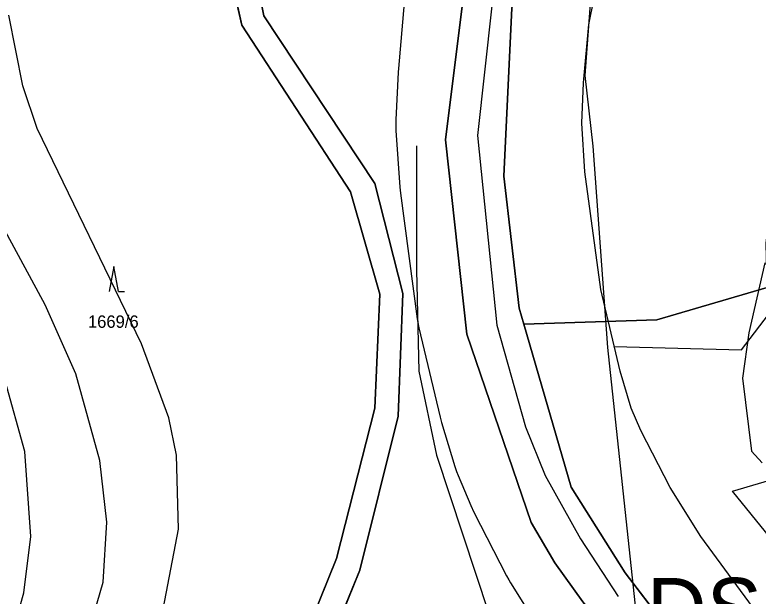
# Model space of a CAD drawing. Extents: x -706130 to -698555, y -971544 to -967260.
# Drawn here: x -704475.2 to -704355.2, y -970876.8 to -970782.9 of the extents above; entities that cross this region are included whole.
import ezdxf

# ---------------------------------------------------------------- set-up
doc = ezdxf.new("R2010")
doc.units = 0
for name, color, linetype in [('KN_Hranice_parcel', 7, 'Continuous'), ('KN_Parcelni cisla', 7, 'Continuous'), ('KN_Polygon parcely', 7, 'Continuous'), ('KN_POZEMKY_10_LESNI POZEMEK', 7, 'Continuous'), ('KN_POZEMKY_14_OSTATNI PLOCHA', 7, 'Continuous'), ('KN_VYUZITI_16_ostatni plocha_silnice', 7, 'Continuous'), ('KN_VYUZITI_17_ostatni plocha_ostatni komunikace', 7, 'Continuous'), ('KN_VYUZITI_26_ostatni plocha_jina plocha', 7, 'Continuous'), ('KN_Značky kultur', 7, 'Continuous'), ('Komunikace III třídy osy S', 7, 'Continuous'), ('OP lesa 30 m', 7, 'Continuous'), ('OP silnic S', 7, 'Continuous'), ('Plochy doprava silniční - silnice III třídy S', 7, 'Continuous'), ('Plochy lesní všeobecné S', 7, 'Continuous'), ('Plochy přírodní - lesní S', 7, 'Continuous'), ('Plochy přírodní - nelesní S', 7, 'Continuous'), ('Plochy těžby nerostů - jiné S', 7, 'Continuous'), ('Regulační bloky v krajině S', 7, 'Continuous'), ('Regulační bloky zastavěné S', 7, 'Continuous'), ('Regulační kódy zastavěné S', 7, 'Continuous'), ('Spoje_dálkový komunikační kabel S', 7, 'Continuous'), ('Trasy cykloturistické N', 7, 'Continuous'), ('USES_BC_mistni S', 7, 'Continuous'), ('USES_ŠRAFY S', 7, 'Continuous'), ('VÝŠKOPIS_vrstevnice doplňková', 7, 'Continuous'), ('VÝŠKOPIS_vrstevnice hlavní', 7, 'Continuous')]:
    doc.layers.add(name, color=color, linetype=linetype)

msp = doc.modelspace()

# ---------------------------------------------------------------- linework, layer by layer
at = {"layer": 'KN_Hranice_parcel'}
for points in [[(-704429.88, -970483.99), (-704437.86, -970500.93), (-704440.81, -970512.35), (-704444.18, -970537.3), (-704437.59, -970564.83), (-704389.48, -970641.61), (-704384.25, -970653.17), (-704379.8, -970666.04), (-704377.6, -970678.33), (-704377.41, -970702.19), (-704385.12, -970737.85), (-704395, -970781.85), (-704396.32, -970808.97), (-704393.81, -970830.29), (-704393.06, -970832.89)], [(-704394.53, -970717.38), (-704412.48, -970734.47), (-704417.24, -970746.67), (-704433.74, -970766.44), (-704437.24, -970771.29), (-704440.06, -970778.03), (-704438.61, -970784.59), (-704421.06, -970811.51), (-704416.31, -970828.02), (-704417.14, -970846.47), (-704423.32, -970870.73), (-704430.14, -970887.7), (-704441.3, -970904.25), (-704468.7, -970937.47), (-704474.31, -970946.68), (-704474.09, -970952.69), (-704473.62, -970956.96), (-704461.41, -971000.71)], [(-704358.88, -970998.11), (-704359.55, -970918.79), (-704364.6, -970901.09), (-704383.52, -970877.76), (-704388.05, -970871.47), (-704391.88, -970864.93), (-704402.29, -970834.53), (-704405.74, -970803.12), (-704402.86, -970780.15), (-704394.94, -970736.25), (-704391.73, -970719.71)], [(-704394.9, -970722.73), (-704407.89, -970735.14), (-704413.08, -970748.41), (-704429.87, -970768.12), (-704434.2, -970773.68), (-704436, -970778.11), (-704435.04, -970783.09), (-704417.14, -970810.17), (-704412.6, -970827.95), (-704413.35, -970847.75), (-704419.53, -970872.65), (-704427.42, -970891.79), (-704435.22, -970903.01), (-704464.78, -970939.11), (-704470.08, -970947.26), (-704470.3, -970952.41), (-704470.15, -970956.87), (-704458.51, -971000.63), (-704450.87, -971043.52)], [(-704393.06, -970832.89), (-704371.61, -970832.19), (-704353.77, -970826.96)], [(-704393.06, -970832.89), (-704385.45, -970859.24), (-704376.72, -970873.06), (-704355.73, -970900.46), (-704350.71, -970916.39), (-704350.59, -970954.64)]]:
    msp.add_lwpolyline(points, dxfattribs=at)
at = {"layer": 'KN_Polygon parcely'}
for points in [[(-704480.71, -970987.86), (-704461.41, -971000.71), (-704473.62, -970956.96), (-704474.09, -970952.69), (-704474.31, -970946.68), (-704468.7, -970937.47), (-704441.3, -970904.25), (-704430.14, -970887.7), (-704423.32, -970870.73), (-704417.14, -970846.47), (-704416.31, -970828.02), (-704421.06, -970811.51), (-704438.61, -970784.59), (-704440.06, -970778.03), (-704437.24, -970771.29), (-704433.74, -970766.44), (-704417.24, -970746.67), (-704412.48, -970734.47), (-704394.53, -970717.38), (-704392.84, -970693.06)], [(-704377.41, -970702.19), (-704385.12, -970737.85), (-704395, -970781.85), (-704396.32, -970808.97), (-704393.81, -970830.29), (-704393.06, -970832.89), (-704371.61, -970832.19), (-704353.77, -970826.96), (-704353.94, -970819.76), (-704348.4, -970775.6), (-704340.41, -970749.09), (-704322.26, -970733.17), (-704314.41, -970716.03), (-704304.49, -970694.37)], [(-704506.42, -971249.39), (-704415.53, -971158.66), (-704407.11, -971148.63), (-704392.41, -971128.82), (-704372.53, -971093.91), (-704363.75, -971071.95), (-704354.41, -971041.91), (-704352.25, -971025.04), (-704351.58, -971019.76), (-704351.31, -971017.68), (-704350.69, -971011.84), (-704350.44, -971008.36), (-704350.59, -970954.64), (-704350.71, -970916.39), (-704355.73, -970900.46), (-704376.72, -970873.06), (-704385.45, -970859.24), (-704393.06, -970832.89), (-704393.81, -970830.29), (-704396.32, -970808.97), (-704395, -970781.85), (-704385.12, -970737.85), (-704377.41, -970702.19)], [(-704389.28, -970704.44), (-704391.73, -970719.71), (-704394.94, -970736.25), (-704402.86, -970780.15), (-704405.74, -970803.12), (-704402.29, -970834.53), (-704391.88, -970864.93), (-704388.05, -970871.47), (-704383.52, -970877.76), (-704364.6, -970901.09), (-704359.55, -970918.79), (-704358.88, -970998.11), (-704360.7, -971028.37), (-704363.13, -971044.43), (-704371.03, -971068.69), (-704379.24, -971088.79), (-704400.72, -971126.52), (-704416.46, -971147.21), (-704421.56, -971152.85), (-704441.18, -971172.34), (-704555.17, -971285.57)], [(-704427.42, -970891.79), (-704419.53, -970872.65), (-704413.35, -970847.75), (-704412.6, -970827.95), (-704417.14, -970810.17), (-704435.04, -970783.09), (-704436, -970778.11), (-704434.2, -970773.68), (-704429.87, -970768.12), (-704413.08, -970748.41), (-704407.89, -970735.14), (-704394.9, -970722.73), (-704394.53, -970717.38), (-704412.48, -970734.47), (-704417.24, -970746.67), (-704433.74, -970766.44), (-704437.24, -970771.29), (-704440.06, -970778.03), (-704438.61, -970784.59), (-704421.06, -970811.51), (-704416.31, -970828.02), (-704417.14, -970846.47), (-704423.32, -970870.73), (-704430.14, -970887.7)], [(-704383.52, -970877.76), (-704388.05, -970871.47), (-704391.88, -970864.93), (-704402.29, -970834.53), (-704405.74, -970803.12), (-704402.86, -970780.15), (-704394.94, -970736.25), (-704391.73, -970719.71), (-704394.9, -970722.73), (-704407.89, -970735.14), (-704413.08, -970748.41), (-704429.87, -970768.12), (-704434.2, -970773.68), (-704436, -970778.11), (-704435.04, -970783.09), (-704417.14, -970810.17), (-704412.6, -970827.95), (-704413.35, -970847.75), (-704419.53, -970872.65), (-704427.42, -970891.79)]]:
    msp.add_lwpolyline(points, dxfattribs=at)
msp.add_lwpolyline([(-704287.09, -970906.43), (-704282.97, -970903.37), (-704293.21, -970894.26), (-704313.53, -970893.02), (-704313.39, -970886.61), (-704313.91, -970882.96), (-704345.87, -970872.27), (-704353.15, -970852.55), (-704353.77, -970826.96), (-704371.61, -970832.19), (-704393.06, -970832.89), (-704385.45, -970859.24), (-704376.72, -970873.06), (-704355.73, -970900.46), (-704350.71, -970916.39), (-704350.59, -970954.64), (-704336.95, -970942.29)], close=True, dxfattribs=at)
at = {"layer": 'KN_POZEMKY_10_LESNI POZEMEK'}
for p, q in [((-704440.06, -970778.03), (-704438.61, -970784.59)), ((-704435.04, -970783.09), (-704436, -970778.11)), ((-704402.86, -970780.15), (-704405.74, -970803.12)), ((-704396.32, -970808.97), (-704395, -970781.85)), ((-704417.14, -970810.17), (-704435.04, -970783.09)), ((-704438.61, -970784.59), (-704421.06, -970811.51)), ((-704405.74, -970803.12), (-704402.29, -970834.53)), ((-704393.81, -970830.29), (-704396.32, -970808.97)), ((-704412.6, -970827.95), (-704417.14, -970810.17)), ((-704421.06, -970811.51), (-704416.31, -970828.02)), ((-704353.77, -970826.96), (-704371.61, -970832.19)), ((-704416.31, -970828.02), (-704417.14, -970846.47)), ((-704413.35, -970847.75), (-704412.6, -970827.95)), ((-704393.06, -970832.89), (-704393.81, -970830.29)), ((-704371.61, -970832.19), (-704393.06, -970832.89)), ((-704402.29, -970834.53), (-704391.88, -970864.93)), ((-704417.14, -970846.47), (-704423.32, -970870.73)), ((-704419.53, -970872.65), (-704413.35, -970847.75)), ((-704391.88, -970864.93), (-704388.05, -970871.47)), ((-704423.32, -970870.73), (-704430.14, -970887.7)), ((-704388.05, -970871.47), (-704383.52, -970877.76)), ((-704427.42, -970891.79), (-704419.53, -970872.65))]:
    msp.add_line(p, q, dxfattribs=at)
at = {"layer": 'KN_POZEMKY_14_OSTATNI PLOCHA'}
for p, q in [((-704438.61, -970784.59), (-704440.06, -970778.03)), ((-704436, -970778.11), (-704435.04, -970783.09)), ((-704405.74, -970803.12), (-704402.86, -970780.15)), ((-704395, -970781.85), (-704396.32, -970808.97)), ((-704435.04, -970783.09), (-704417.14, -970810.17)), ((-704421.06, -970811.51), (-704438.61, -970784.59)), ((-704402.29, -970834.53), (-704405.74, -970803.12)), ((-704396.32, -970808.97), (-704393.81, -970830.29)), ((-704417.14, -970810.17), (-704412.6, -970827.95)), ((-704416.31, -970828.02), (-704421.06, -970811.51)), ((-704371.61, -970832.19), (-704353.77, -970826.96)), ((-704417.14, -970846.47), (-704416.31, -970828.02)), ((-704412.6, -970827.95), (-704413.35, -970847.75)), ((-704393.81, -970830.29), (-704393.06, -970832.89)), ((-704393.06, -970832.89), (-704371.61, -970832.19)), ((-704393.06, -970832.89), (-704385.45, -970859.24)), ((-704385.45, -970859.24), (-704393.06, -970832.89)), ((-704391.88, -970864.93), (-704402.29, -970834.53)), ((-704423.32, -970870.73), (-704417.14, -970846.47)), ((-704413.35, -970847.75), (-704419.53, -970872.65)), ((-704385.45, -970859.24), (-704376.72, -970873.06)), ((-704376.72, -970873.06), (-704385.45, -970859.24)), ((-704388.05, -970871.47), (-704391.88, -970864.93)), ((-704430.14, -970887.7), (-704423.32, -970870.73)), ((-704383.52, -970877.76), (-704388.05, -970871.47)), ((-704419.53, -970872.65), (-704427.42, -970891.79)), ((-704376.72, -970873.06), (-704355.73, -970900.46)), ((-704355.73, -970900.46), (-704376.72, -970873.06))]:
    msp.add_line(p, q, dxfattribs=at)
at = {"layer": 'KN_VYUZITI_16_ostatni plocha_silnice'}
for p, q in [((-704405.74, -970803.12), (-704402.86, -970780.15)), ((-704395, -970781.85), (-704396.32, -970808.97)), ((-704402.29, -970834.53), (-704405.74, -970803.12)), ((-704396.32, -970808.97), (-704393.81, -970830.29)), ((-704393.81, -970830.29), (-704393.06, -970832.89)), ((-704393.06, -970832.89), (-704385.45, -970859.24)), ((-704391.88, -970864.93), (-704402.29, -970834.53)), ((-704385.45, -970859.24), (-704376.72, -970873.06)), ((-704388.05, -970871.47), (-704391.88, -970864.93)), ((-704383.52, -970877.76), (-704388.05, -970871.47)), ((-704376.72, -970873.06), (-704355.73, -970900.46))]:
    msp.add_line(p, q, dxfattribs=at)
at = {"layer": 'KN_VYUZITI_17_ostatni plocha_ostatni komunikace'}
for p, q in [((-704438.61, -970784.59), (-704440.06, -970778.03)), ((-704436, -970778.11), (-704435.04, -970783.09)), ((-704435.04, -970783.09), (-704417.14, -970810.17)), ((-704421.06, -970811.51), (-704438.61, -970784.59)), ((-704417.14, -970810.17), (-704412.6, -970827.95)), ((-704416.31, -970828.02), (-704421.06, -970811.51)), ((-704417.14, -970846.47), (-704416.31, -970828.02)), ((-704412.6, -970827.95), (-704413.35, -970847.75)), ((-704423.32, -970870.73), (-704417.14, -970846.47)), ((-704413.35, -970847.75), (-704419.53, -970872.65)), ((-704430.14, -970887.7), (-704423.32, -970870.73)), ((-704419.53, -970872.65), (-704427.42, -970891.79))]:
    msp.add_line(p, q, dxfattribs=at)
at = {"layer": 'KN_VYUZITI_26_ostatni plocha_jina plocha'}
for p, q in [((-704371.61, -970832.19), (-704353.77, -970826.96)), ((-704393.06, -970832.89), (-704371.61, -970832.19)), ((-704385.45, -970859.24), (-704393.06, -970832.89)), ((-704376.72, -970873.06), (-704385.45, -970859.24)), ((-704355.73, -970900.46), (-704376.72, -970873.06))]:
    msp.add_line(p, q, dxfattribs=at)
at = {"layer": 'KN_Značky kultur'}
for p, q in [((-704459.28, -970823.6), (-704460.03, -970827.6)), ((-704458.53, -970827.6), (-704459.28, -970823.6)), ((-704458.53, -970827.6), (-704457.53, -970827.6))]:
    msp.add_line(p, q, dxfattribs=at)
at = {"layer": 'Komunikace III třídy osy S'}
for points in [[(-704381.65, -970699.6), (-704384.78, -970713.86), (-704392.65, -970751.27), (-704396.61, -970770.87), (-704398.25, -970781.45), (-704400.54, -970802.4)], [(-704400.54, -970802.4), (-704397.4, -970833.06), (-704392.82, -970849.5), (-704389.61, -970857.36), (-704383.9, -970867.59), (-704377.82, -970876.88)]]:
    msp.add_lwpolyline(points, dxfattribs=at)
at = {"layer": 'OP lesa 30 m'}
msp.add_lwpolyline([(-704341.3, -970882.19), (-704359.4, -970859.87), (-704345.33, -970855.75)], dxfattribs=at)
at = {"layer": 'OP silnic S'}
for points in [[(-704348.41, -970889.09), (-704364.5, -970867.21), (-704369.46, -970859.29), (-704374.2, -970850.07), (-704375.72, -970846.46), (-704377.51, -970840.51), (-704380.66, -970827.29), (-704383.2, -970808.26), (-704383.73, -970800.43), (-704383.41, -970793.89), (-704382.59, -970784.46), (-704380.84, -970775.93), (-704376.27, -970754.83), (-704367.4, -970715.22), (-704367.27, -970714.55), (-704367.21, -970714.21), (-704365.16, -970700.81)], [(-704412.4, -970781), (-704413.32, -970791.58), (-704413.36, -970792.16), (-704413.73, -970799.86), (-704413.75, -970800.58), (-704413.72, -970801.59), (-704413.1, -970810.77), (-704413, -970811.74), (-704410.3, -970832.01), (-704410.2, -970832.64), (-704410.02, -970833.51), (-704406.59, -970847.9), (-704406.36, -970848.76), (-704404.21, -970855.88), (-704403.95, -970856.67), (-704403.69, -970857.34), (-704401.65, -970862.21), (-704401.15, -970863.27), (-704395.85, -970873.57), (-704395.5, -970874.21), (-704395.22, -970874.67), (-704389.63, -970883.6)]]:
    msp.add_lwpolyline(points, dxfattribs=at)
at = {"layer": 'Plochy doprava silniční - silnice III třídy S'}
for p, q in [((-704402.86, -970780.15), (-704405.74, -970803.12)), ((-704396.32, -970808.97), (-704395, -970781.85)), ((-704405.74, -970803.12), (-704402.29, -970834.53)), ((-704393.81, -970830.29), (-704396.32, -970808.97)), ((-704393.06, -970832.89), (-704393.81, -970830.29)), ((-704385.45, -970859.24), (-704393.06, -970832.89)), ((-704402.29, -970834.53), (-704391.88, -970864.93)), ((-704376.72, -970873.06), (-704385.45, -970859.24)), ((-704391.88, -970864.93), (-704388.05, -970871.47)), ((-704388.05, -970871.47), (-704383.52, -970877.76)), ((-704355.73, -970900.46), (-704376.72, -970873.06))]:
    msp.add_line(p, q, dxfattribs=at)
at = {"layer": 'Plochy lesní všeobecné S'}
for p, q in [((-704395, -970781.85), (-704396.32, -970808.97)), ((-704396.32, -970808.97), (-704393.81, -970830.29)), ((-704371.61, -970832.19), (-704353.77, -970826.96)), ((-704393.81, -970830.29), (-704393.06, -970832.89)), ((-704393.06, -970832.89), (-704371.61, -970832.19))]:
    msp.add_line(p, q, dxfattribs=at)
at = {"layer": 'Plochy přírodní - lesní S'}
for p, q in [((-704436, -970778.11), (-704435.04, -970783.09)), ((-704436, -970778.11), (-704435.04, -970783.09)), ((-704405.74, -970803.12), (-704402.86, -970780.15)), ((-704405.74, -970803.12), (-704402.86, -970780.15)), ((-704435.04, -970783.09), (-704417.14, -970810.17)), ((-704435.04, -970783.09), (-704417.14, -970810.17)), ((-704402.29, -970834.53), (-704405.74, -970803.12)), ((-704402.29, -970834.53), (-704405.74, -970803.12)), ((-704417.14, -970810.17), (-704412.6, -970827.95)), ((-704417.14, -970810.17), (-704412.6, -970827.95)), ((-704416.31, -970828.02), (-704421.06, -970811.51)), ((-704417.14, -970846.47), (-704416.31, -970828.02)), ((-704412.6, -970827.95), (-704413.35, -970847.75)), ((-704412.6, -970827.95), (-704413.35, -970847.75)), ((-704391.88, -970864.93), (-704402.29, -970834.53)), ((-704391.88, -970864.93), (-704402.29, -970834.53)), ((-704413.35, -970847.75), (-704419.53, -970872.65)), ((-704413.35, -970847.75), (-704419.53, -970872.65)), ((-704388.05, -970871.47), (-704391.88, -970864.93)), ((-704388.05, -970871.47), (-704391.88, -970864.93)), ((-704383.52, -970877.76), (-704388.05, -970871.47)), ((-704383.52, -970877.76), (-704388.05, -970871.47)), ((-704419.53, -970872.65), (-704427.42, -970891.79)), ((-704419.53, -970872.65), (-704427.42, -970891.79))]:
    msp.add_line(p, q, dxfattribs=at)
for points in [[(-704421.06, -970811.51), (-704438.61, -970784.59), (-704440.06, -970778.03)], [(-704430.14, -970887.7), (-704423.32, -970870.73), (-704417.14, -970846.47)]]:
    msp.add_lwpolyline(points, dxfattribs=at)
at = {"layer": 'Plochy přírodní - nelesní S'}
for p, q in [((-704440.06, -970778.03), (-704438.61, -970784.59)), ((-704435.04, -970783.09), (-704436, -970778.11)), ((-704417.14, -970810.17), (-704435.04, -970783.09)), ((-704438.61, -970784.59), (-704421.06, -970811.51)), ((-704412.6, -970827.95), (-704417.14, -970810.17)), ((-704421.06, -970811.51), (-704416.31, -970828.02)), ((-704416.31, -970828.02), (-704417.14, -970846.47)), ((-704413.35, -970847.75), (-704412.6, -970827.95))]:
    msp.add_line(p, q, dxfattribs=at)
for points in [[(-704417.14, -970846.47), (-704423.32, -970870.73), (-704430.14, -970887.7), (-704441.3, -970904.25)], [(-704427.42, -970891.79), (-704419.53, -970872.65), (-704413.35, -970847.75)]]:
    msp.add_lwpolyline(points, dxfattribs=at)
at = {"layer": 'Plochy těžby nerostů - jiné S'}
for p, q in [((-704353.77, -970826.96), (-704371.61, -970832.19)), ((-704371.61, -970832.19), (-704393.06, -970832.89)), ((-704393.06, -970832.89), (-704385.45, -970859.24)), ((-704385.45, -970859.24), (-704376.72, -970873.06)), ((-704376.72, -970873.06), (-704355.73, -970900.46))]:
    msp.add_line(p, q, dxfattribs=at)
at = {"layer": 'Regulační bloky v krajině S'}
for p, q in [((-704405.74, -970803.12), (-704402.86, -970780.15)), ((-704395, -970781.85), (-704396.32, -970808.97)), ((-704402.29, -970834.53), (-704405.74, -970803.12)), ((-704396.32, -970808.97), (-704393.81, -970830.29)), ((-704371.61, -970832.19), (-704353.77, -970826.96)), ((-704353.77, -970826.96), (-704371.61, -970832.19)), ((-704393.81, -970830.29), (-704393.06, -970832.89)), ((-704393.06, -970832.89), (-704371.61, -970832.19)), ((-704371.61, -970832.19), (-704393.06, -970832.89)), ((-704393.06, -970832.89), (-704385.45, -970859.24)), ((-704391.88, -970864.93), (-704402.29, -970834.53)), ((-704385.45, -970859.24), (-704376.72, -970873.06)), ((-704388.05, -970871.47), (-704391.88, -970864.93)), ((-704383.52, -970877.76), (-704388.05, -970871.47)), ((-704376.72, -970873.06), (-704355.73, -970900.46))]:
    msp.add_line(p, q, dxfattribs=at)
at = {"layer": 'Regulační bloky zastavěné S'}
for p, q in [((-704402.86, -970780.15), (-704405.74, -970803.12)), ((-704396.32, -970808.97), (-704395, -970781.85)), ((-704405.74, -970803.12), (-704402.29, -970834.53)), ((-704393.81, -970830.29), (-704396.32, -970808.97)), ((-704393.06, -970832.89), (-704393.81, -970830.29)), ((-704385.45, -970859.24), (-704393.06, -970832.89)), ((-704402.29, -970834.53), (-704391.88, -970864.93)), ((-704376.72, -970873.06), (-704385.45, -970859.24)), ((-704391.88, -970864.93), (-704388.05, -970871.47)), ((-704388.05, -970871.47), (-704383.52, -970877.76)), ((-704355.73, -970900.46), (-704376.72, -970873.06))]:
    msp.add_line(p, q, dxfattribs=at)
at = {"layer": 'Spoje_dálkový komunikační kabel S'}
msp.add_lwpolyline([(-704354.14, -970822.98), (-704356.73, -970834.27), (-704357.79, -970841.59), (-704356.29, -970853.39), (-704354.61, -970855.29)], dxfattribs=at)
at = {"layer": 'Trasy cykloturistické N'}
msp.add_lwpolyline([(-704506.42, -971249.39), (-704415.53, -971158.66), (-704407.11, -971148.63), (-704392.41, -971128.82), (-704372.53, -971093.91), (-704363.75, -971071.95), (-704354.41, -971041.91), (-704351.58, -971019.76), (-704350.44, -971008.36), (-704350.59, -970954.64), (-704350.71, -970916.39), (-704355.73, -970900.46), (-704376.72, -970873.06), (-704385.45, -970859.24), (-704393.06, -970832.89), (-704393.81, -970830.29), (-704396.32, -970808.97), (-704395, -970781.85), (-704385.12, -970737.85), (-704377.41, -970702.19)], dxfattribs=at)
at = {"layer": 'USES_BC_mistni S'}
msp.add_lwpolyline([(-704498.2, -970931.97), (-704466.58, -970970.29), (-704458.51, -971000.63), (-704450.87, -971043.52), (-704448.75, -971041.07), (-704425.92, -971019.27), (-704405.29, -971004.68), (-704395.98, -970998.1), (-704388.29, -970984.51), (-704377.9, -970979.05), (-704364.9, -970980.93), (-704358.88, -970998.11), (-704359.55, -970918.79), (-704364.6, -970901.09), (-704383.52, -970877.76), (-704388.05, -970871.47), (-704391.88, -970864.93), (-704402.29, -970834.53), (-704405.74, -970803.12), (-704402.86, -970780.15), (-704394.94, -970736.25), (-704391.73, -970719.71), (-704389.28, -970704.44)], dxfattribs=at)
at = {"layer": 'USES_ŠRAFY S'}
msp.add_lwpolyline([(-704498.2, -970931.97), (-704466.58, -970970.29), (-704458.51, -971000.63), (-704450.87, -971043.52), (-704448.75, -971041.07), (-704425.92, -971019.27), (-704405.29, -971004.68), (-704395.98, -970998.1), (-704388.29, -970984.51), (-704377.9, -970979.05), (-704364.9, -970980.93), (-704358.88, -970998.11), (-704359.55, -970918.79), (-704364.6, -970901.09), (-704383.52, -970877.76), (-704388.05, -970871.47), (-704391.88, -970864.93), (-704402.29, -970834.53), (-704405.74, -970803.12), (-704402.86, -970780.15), (-704394.94, -970736.25), (-704391.73, -970719.71), (-704389.28, -970704.44)], dxfattribs=at)
at = {"layer": 'VÝŠKOPIS_vrstevnice doplňková'}
msp.add_lwpolyline([(-704378.49, -970836.51), (-704357.94, -970837.05), (-704347.82, -970823.77), (-704344.61, -970818.11), (-704339.37, -970805.62), (-704335.96, -970801.22), (-704333.23, -970795.24), (-704332.64, -970791.31), (-704329.73, -970783.95)], dxfattribs=at)
at = {"layer": 'VÝŠKOPIS_vrstevnice hlavní'}
for points in [[(-704349.1, -970701.1), (-704357.81, -970721.65), (-704374.5, -970753.6), (-704378.49, -970763.02), (-704382.06, -970776.72), (-704383.2, -970792.7), (-704381.92, -970804.11), (-704379.58, -970836.64)], [(-704479.93, -970928.38), (-704469.95, -970917.96), (-704464.67, -970911.11), (-704458.74, -970901.91), (-704455.39, -970893.99), (-704452.25, -970884.01), (-704448.83, -970866.03), (-704449.12, -970854.04), (-704450.4, -970848.05), (-704454.82, -970836.07), (-704471.66, -970801.26), (-704473.94, -970794.41), (-704476.22, -970782.99)], [(-704410.38, -970804.1), (-704410.38, -970824.19), (-704410.02, -970840.49), (-704407.17, -970854.04), (-704396.61, -970886), (-704396.61, -970896.85), (-704399.61, -970903.41), (-704401.03, -970905.12), (-704405.74, -970908.4), (-704425.57, -970919.39), (-704438.27, -970927.38), (-704455.96, -970941.93), (-704465.81, -970947.49), (-704472.51, -970949.21), (-704485.07, -970949.06)], [(-704481.93, -970916.53), (-704472.94, -970903.69), (-704464.95, -970888.29), (-704460.96, -970874.59), (-704460.39, -970864.89), (-704461.53, -970854.9), (-704465.38, -970840.92), (-704470.37, -970829.79), (-704481.5, -970809.25)], [(-704379.58, -970836.64), (-704372.64, -970901.55), (-704372.79, -970906.83), (-704374.78, -970910.97), (-704381.06, -970918.25), (-704384.63, -970920.39), (-704388.91, -970921.96), (-704400.32, -970923.67), (-704409.03, -970926.24), (-704431.99, -970938.51), (-704440.84, -970944.78), (-704447.69, -970951.49), (-704459.53, -970965.04), (-704463.38, -970968.18), (-704464.95, -970968.75), (-704470.52, -970968.61), (-704486.21, -970965.61)], [(-704476.37, -970885.43), (-704473.8, -970876.3), (-704472.66, -970867.17), (-704473.65, -970853.47), (-704476.79, -970842.06)]]:
    msp.add_lwpolyline(points, dxfattribs=at)

# ---------------------------------------------------------------- texts
at = {"layer": 'KN_Parcelni cisla'}
msp.add_text('1669/6', height=2, dxfattribs=at).set_placement((-704463.44, -970833.48))
at = {"layer": 'Regulační kódy zastavěné S'}
msp.add_text('DS', height=10, dxfattribs=at).set_placement((-704373.21, -970883.89))

doc.saveas('drawing.dxf')
